Omron CX-Programmer project NuevoProyecto (CX-Programmer 9.50)

# PLC NewPLC1: CP1L-E EM

## Program P13 (cyclic task 0)
Local symbols
AL 100.02 BOOL
Etapa_0 10.00 BOOL
Etapa_1 10.01 BOOL
Etapa_2 10.02 BOOL
Etapa_3 10.03 BOOL
Etapa_4 10.04 BOOL
Etapa_5 10.05 BOOL
Etapa_6 10.06 BOOL
Etapa_7 10.07 BOOL
Etapa_8 10.08 BOOL
Etapa_9 10.09 BOOL
F1 0.01 BOOL
F2 0.02 BOOL
K1 100.00 BOOL
K2 100.01 BOOL
S_1 0.03 BOOL
S_2 0.04 BOOL
m 0.00 BOOL

### Section Sección1_Programa_principal
; Etapas 0 ... 9

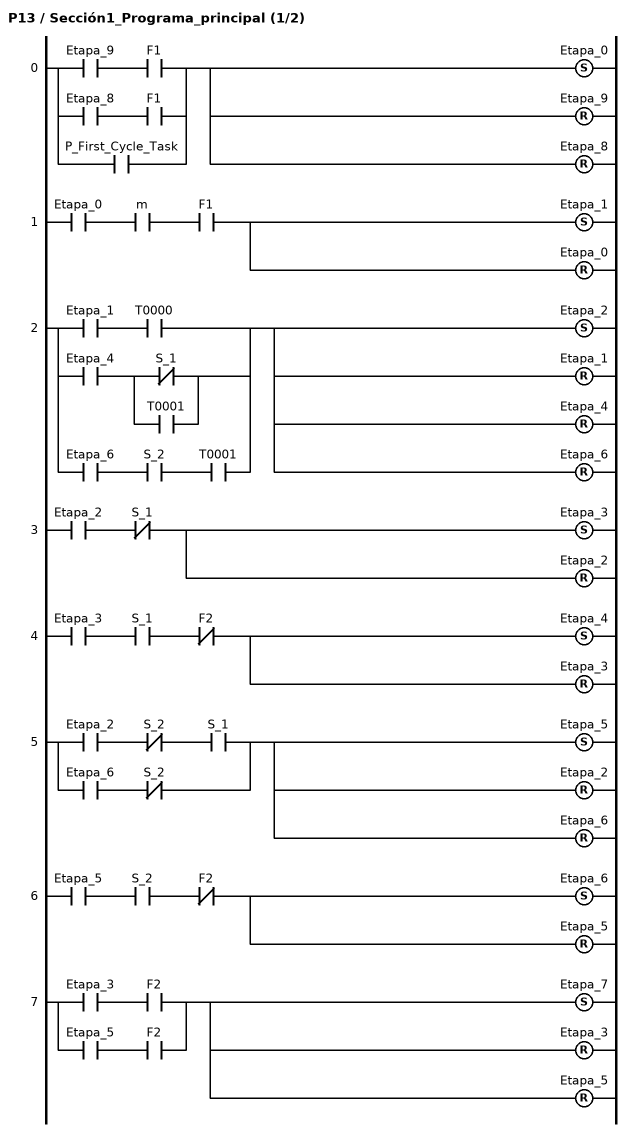
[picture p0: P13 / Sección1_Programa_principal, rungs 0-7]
; rung 0
LD Etapa_9
AND F1
LD Etapa_8
AND F1
ORLD
OR P_First_Cycle_Task
SET Etapa_0
RSET Etapa_9
RSET Etapa_8
; rung 1
LD Etapa_0
AND m
AND F1
SET Etapa_1
RSET Etapa_0
; rung 2
LD Etapa_1
AND T0000
LD Etapa_4
LDNOT S_1
OR T0001
ANDLD
ORLD
LD Etapa_6
AND S_2
AND T0001
ORLD
SET Etapa_2
RSET Etapa_1
RSET Etapa_4
RSET Etapa_6
; rung 3
LD Etapa_2
ANDNOT S_1
SET Etapa_3
RSET Etapa_2
; rung 4
LD Etapa_3
AND S_1
ANDNOT F2
SET Etapa_4
RSET Etapa_3
; rung 5
LD Etapa_2
ANDNOT S_2
AND S_1
LD Etapa_6
ANDNOT S_2
ORLD
SET Etapa_5
RSET Etapa_2
RSET Etapa_6
; rung 6
LD Etapa_5
AND S_2
ANDNOT F2
SET Etapa_6
RSET Etapa_5
; rung 7
LD Etapa_3
AND F2
LD Etapa_5
AND F2
ORLD
SET Etapa_7
RSET Etapa_3
RSET Etapa_5

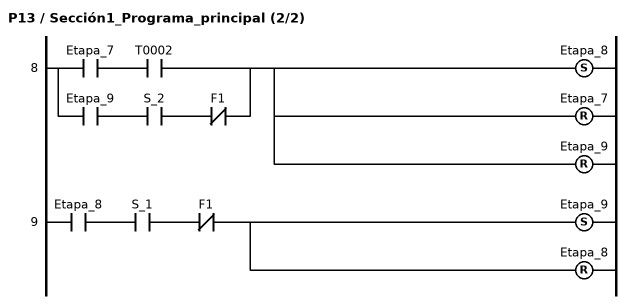
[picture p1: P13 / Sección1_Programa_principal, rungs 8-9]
; rung 8
LD Etapa_7
AND T0002
LD Etapa_9
AND S_2
ANDNOT F1
ORLD
SET Etapa_8
RSET Etapa_7
RSET Etapa_9
; rung 9
LD Etapa_8
AND S_1
ANDNOT F1
SET Etapa_9
RSET Etapa_8

### Section Sección2_Temporizadores

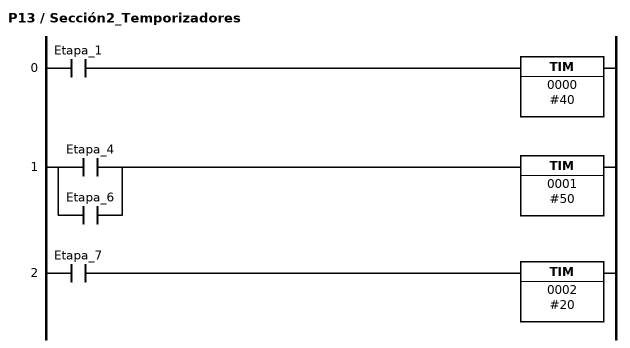
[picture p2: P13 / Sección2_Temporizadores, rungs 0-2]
; rung 0
LD Etapa_1
TIM 0000 #40
; rung 1
LD Etapa_4
OR Etapa_6
TIM 0001 #50
; rung 2
LD Etapa_7
TIM 0002 #20

### Section Sección3_Salidas
; Salidas

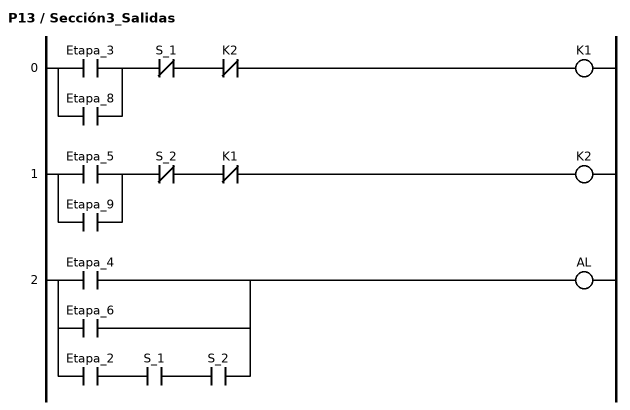
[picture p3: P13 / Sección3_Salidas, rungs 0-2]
; rung 0
LD Etapa_3
OR Etapa_8
ANDNOT S_1
ANDNOT K2
OUT K1
; rung 1
LD Etapa_5
OR Etapa_9
ANDNOT S_2
ANDNOT K1
OUT K2
; rung 2
LD Etapa_4
OR Etapa_6
LD Etapa_2
AND S_1
AND S_2
ORLD
OUT AL

### Section Sección4_END
; rung 0
END(001)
